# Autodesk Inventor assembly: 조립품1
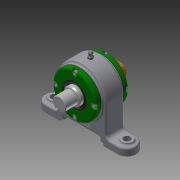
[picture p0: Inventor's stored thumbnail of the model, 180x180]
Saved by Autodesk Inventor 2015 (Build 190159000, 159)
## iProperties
Created: 2019-05
Part Number: 조립품1
Document SubType Name: Assembly
Designer: 102101
Author: 102101
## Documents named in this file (13)
- C:\Users\102101\Desktop\490504V1036\조립품1.iam
- C:\Users\102101\Desktop\490504V1036\개스킷.ipt
- C:\Users\102101\Desktop\490504V1036\그리스니플 M6.ipt
- 그리스니플  M6.ipt
- C:\Users\102101\Desktop\490504V1036\그리스니플개스킷.ipt
- C:\Users\102101\Desktop\490504V1036\베어링너트.ipt
- C:\Users\102101\Desktop\490504V1036\본체.ipt
- C:\Users\102101\Desktop\490504V1036\볼트 M4.ipt
- C:\Users\102101\Desktop\490504V1036\앵귤러 볼 베어링 7205.ipt
- C:\Users\102101\Desktop\490504V1036\오일 실 28 40 5 B.ipt
- C:\Users\102101\Desktop\490504V1036\축.ipt
- C:\Users\102101\Desktop\490504V1036\칼라.ipt
- C:\Users\102101\Desktop\490504V1036\커버.ipt
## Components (4 placed, 3 different names)
1. 개스킷:1
2. 그리스니플  M6:1
3. 그리스니플개스킷:1
4. 개스킷:2
